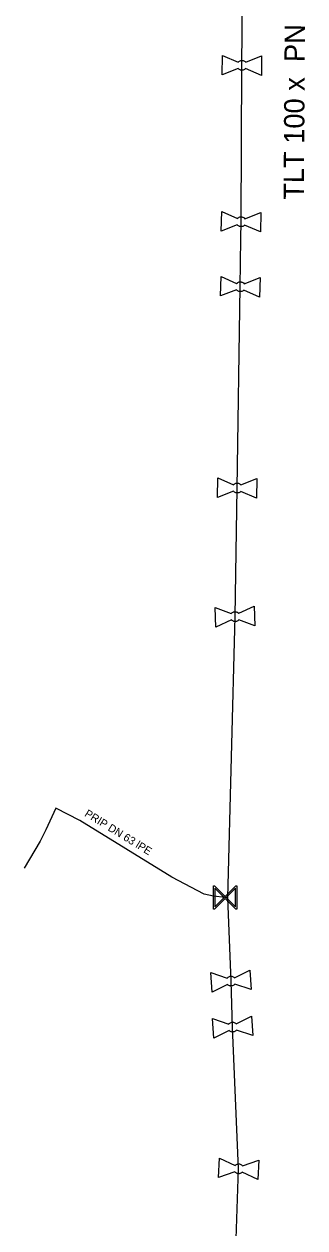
# Model space of a CAD drawing. Extents: x -643842 to -636370, y -1119190 to -1110210.
# Drawn here: x -641952.7 to -641934.8, y -1115378.3 to -1115301.5 of the extents above; entities that cross this region are included whole.
import ezdxf

# ---------------------------------------------------------------- set-up
doc = ezdxf.new("R2010")
doc.units = 0
for name, color, linetype in [('22', 7, 'Continuous'), ('Default', 7, 'Continuous'), ('Level 16', 7, 'Continuous'), ('Level 20', 7, 'Continuous'), ('Level 21', 7, 'Continuous'), ('Level 23', 7, 'Continuous'), ('Level 28', 7, 'Continuous')]:
    doc.layers.add(name, color=color, linetype=linetype)

msp = doc.modelspace()

# ---------------------------------------------------------------- linework, layer by layer
at = {"layer": 'Default'}
for points in [[(-641939.014, -1115303.883), (-641938.98, -1115303.843), (-641938.932, -1115303.817), (-641938.858, -1115303.776), (-641938.776, -1115303.778), (-641938.694, -1115303.779), (-641938.619, -1115303.822), (-641938.573, -1115303.848), (-641938.539, -1115303.889)], [(-641938.545, -1115304.298), (-641938.579, -1115304.337), (-641938.626, -1115304.363), (-641938.702, -1115304.404), (-641938.784, -1115304.402), (-641938.866, -1115304.401), (-641938.938, -1115304.359), (-641938.986, -1115304.332), (-641939.019, -1115304.291)], [(-641939.072, -1115313.871), (-641939.037, -1115313.831), (-641938.989, -1115313.806), (-641938.915, -1115313.766), (-641938.833, -1115313.768), (-641938.751, -1115313.769), (-641938.676, -1115313.814), (-641938.631, -1115313.841), (-641938.597, -1115313.882)], [(-641938.607, -1115314.29), (-641938.642, -1115314.329), (-641938.689, -1115314.355), (-641938.765, -1115314.394), (-641938.847, -1115314.392), (-641938.929, -1115314.391), (-641939.001, -1115314.347), (-641939.048, -1115314.319), (-641939.081, -1115314.278)], [(-641939.12, -1115318.019), (-641939.085, -1115317.979), (-641939.036, -1115317.954), (-641938.962, -1115317.915), (-641938.88, -1115317.918), (-641938.798, -1115317.92), (-641938.724, -1115317.965), (-641938.678, -1115317.993), (-641938.645, -1115318.034)], [(-641938.659, -1115318.443), (-641938.694, -1115318.481), (-641938.741, -1115318.506), (-641938.818, -1115318.545), (-641938.9, -1115318.542), (-641938.982, -1115318.54), (-641939.054, -1115318.496), (-641939.1, -1115318.467), (-641939.133, -1115318.426)], [(-641939.323, -1115330.882), (-641939.289, -1115330.843), (-641939.241, -1115330.817), (-641939.167, -1115330.776), (-641939.085, -1115330.778), (-641939.003, -1115330.779), (-641938.928, -1115330.823), (-641938.882, -1115330.849), (-641938.849, -1115330.89)], [(-641938.855, -1115331.299), (-641938.89, -1115331.337), (-641938.937, -1115331.364), (-641939.013, -1115331.404), (-641939.095, -1115331.402), (-641939.177, -1115331.401), (-641939.249, -1115331.358), (-641939.297, -1115331.331), (-641939.33, -1115331.29)], [(-641939.464, -1115339.105), (-641939.431, -1115339.063), (-641939.385, -1115339.035), (-641939.313, -1115338.991), (-641939.231, -1115338.988), (-641939.15, -1115338.985), (-641939.072, -1115339.025), (-641939.025, -1115339.049), (-641938.989, -1115339.088)], [(-641938.975, -1115339.496), (-641939.007, -1115339.537), (-641939.053, -1115339.565), (-641939.127, -1115339.609), (-641939.209, -1115339.612), (-641939.29, -1115339.615), (-641939.365, -1115339.576), (-641939.414, -1115339.551), (-641939.449, -1115339.512)], [(-641939.729, -1115362.392), (-641939.698, -1115362.349), (-641939.652, -1115362.32), (-641939.582, -1115362.273), (-641939.5, -1115362.268), (-641939.419, -1115362.263), (-641939.34, -1115362.301), (-641939.292, -1115362.323), (-641939.256, -1115362.361)], [(-641939.229, -1115362.769), (-641939.261, -1115362.81), (-641939.305, -1115362.84), (-641939.378, -1115362.887), (-641939.46, -1115362.892), (-641939.541, -1115362.897), (-641939.617, -1115362.86), (-641939.666, -1115362.837), (-641939.703, -1115362.799)], [(-641939.629, -1115365.332), (-641939.598, -1115365.289), (-641939.552, -1115365.259), (-641939.481, -1115365.213), (-641939.4, -1115365.208), (-641939.318, -1115365.203), (-641939.24, -1115365.241), (-641939.192, -1115365.263), (-641939.155, -1115365.301)], [(-641939.129, -1115365.71), (-641939.161, -1115365.751), (-641939.206, -1115365.78), (-641939.279, -1115365.827), (-641939.36, -1115365.832), (-641939.442, -1115365.837), (-641939.518, -1115365.8), (-641939.567, -1115365.777), (-641939.603, -1115365.738)], [(-641938.763, -1115374.787), (-641938.799, -1115374.825), (-641938.847, -1115374.849), (-641938.925, -1115374.886), (-641939.007, -1115374.882), (-641939.088, -1115374.878), (-641939.159, -1115374.832), (-641939.205, -1115374.803), (-641939.237, -1115374.761)], [(-641939.216, -1115374.354), (-641939.179, -1115374.315), (-641939.13, -1115374.291), (-641939.055, -1115374.254), (-641938.973, -1115374.258), (-641938.892, -1115374.262), (-641938.818, -1115374.309), (-641938.773, -1115374.337), (-641938.741, -1115374.379)]]:
    msp.add_open_spline(points, degree=3, dxfattribs=at)
at = {"layer": 'Level 16'}
for points in [[(-641940.6, -1115357.99), (-641940.6, -1115356.49), (-641940.534, -1115356.49), (-641940.446, -1115356.584), (-641939.851, -1115357.177), (-641939.166, -1115356.49), (-641939.1, -1115356.49), (-641939.1, -1115357.99), (-641939.166, -1115357.99), (-641939.851, -1115357.302), (-641940.445, -1115357.896), (-641940.534, -1115357.99), (-641940.6, -1115357.99)], [(-641940.506, -1115357.832), (-641939.914, -1115357.239), (-641940.506, -1115356.648), (-641940.506, -1115357.832)], [(-641939.194, -1115356.643), (-641939.789, -1115357.239), (-641939.194, -1115357.833), (-641939.194, -1115356.643)]]:
    msp.add_lwpolyline(points, dxfattribs=at)
at = {"layer": 'Level 21'}
msp.add_lwpolyline([(-641939.2, -1115380.32), (-641938.99, -1115374.57), (-641939.38, -1115365.52), (-641939.48, -1115362.58), (-641939.69, -1115357.26), (-641939.22, -1115339.3), (-641939.09, -1115331.09), (-641938.89, -1115318.23), (-641938.86, -1115315.16), (-641938.84, -1115314.08), (-641938.78, -1115304.09), (-641938.75, -1115299.71)], dxfattribs=at)
at = {"layer": 'Level 23'}
msp.add_lwpolyline([(-641939.69, -1115357.26), (-641939.85, -1115357.24), (-641940.6, -1115357.16), (-641941.19, -1115357.02), (-641943.264, -1115355.948), (-641949.15, -1115352.33), (-641950.68, -1115351.53), (-641951.32, -1115352.92), (-641951.68, -1115353.64), (-641952.708, -1115355.356)], dxfattribs=at)
at = {"layer": 'Level 28'}
for points in [[(-641939.019, -1115304.291), (-641940.038, -1115304.699), (-641940.022, -1115303.449), (-641939.014, -1115303.883)], [(-641937.522, -1115303.481), (-641937.538, -1115304.731), (-641938.545, -1115304.298)], [(-641938.539, -1115303.889), (-641937.522, -1115303.481)], [(-641939.081, -1115314.278), (-641940.104, -1115314.676), (-641940.075, -1115313.427), (-641939.072, -1115313.871)], [(-641937.576, -1115313.484), (-641937.605, -1115314.733), (-641938.607, -1115314.29)], [(-641938.597, -1115313.882), (-641937.576, -1115313.484)], [(-641939.133, -1115318.426), (-641940.16, -1115318.814), (-641940.119, -1115317.565), (-641939.12, -1115318.019)], [(-641937.62, -1115317.646), (-641937.661, -1115318.895), (-641938.659, -1115318.443)], [(-641938.645, -1115318.034), (-641937.62, -1115317.646)], [(-641939.33, -1115331.29), (-641940.35, -1115331.694), (-641940.33, -1115330.445), (-641939.323, -1115330.882)], [(-641937.83, -1115330.486), (-641937.85, -1115331.735), (-641938.855, -1115331.299)], [(-641938.849, -1115330.89), (-641937.83, -1115330.486)], [(-641939.449, -1115339.512), (-641940.447, -1115339.97), (-641940.492, -1115338.72), (-641939.464, -1115339.105)], [(-641938.989, -1115339.088), (-641937.993, -1115338.63)], [(-641937.993, -1115338.63), (-641937.948, -1115339.88), (-641938.975, -1115339.496)], [(-641939.703, -1115362.799), (-641940.687, -1115363.284), (-641940.768, -1115362.037), (-641939.729, -1115362.392)], [(-641939.256, -1115362.361), (-641938.273, -1115361.876)], [(-641938.273, -1115361.876), (-641938.192, -1115363.123), (-641939.229, -1115362.769)], [(-641939.155, -1115365.301), (-641938.172, -1115364.817)], [(-641938.172, -1115364.817), (-641938.093, -1115366.064), (-641939.129, -1115365.71)], [(-641939.603, -1115365.738), (-641940.588, -1115366.223), (-641940.667, -1115364.976), (-641939.629, -1115365.332)], [(-641939.237, -1115374.761), (-641940.271, -1115375.128), (-641940.205, -1115373.879), (-641939.216, -1115374.354)], [(-641937.709, -1115374.012), (-641937.775, -1115375.261), (-641938.763, -1115374.787)], [(-641938.741, -1115374.379), (-641937.709, -1115374.012)]]:
    msp.add_lwpolyline(points, dxfattribs=at)

# ---------------------------------------------------------------- texts
at = {"layer": '22'}
msp.add_text('PRIP DN 63 lPE', height=0.5, rotation=328.42537, dxfattribs=at).set_placement((-641948.883, -1115352.012))
at = {"layer": 'Level 20'}
msp.add_text('TLT 100 x  PN ', height=1.3, rotation=89.65589, dxfattribs=at).set_placement((-641934.82, -1115312.674))

doc.saveas('drawing.dxf')
